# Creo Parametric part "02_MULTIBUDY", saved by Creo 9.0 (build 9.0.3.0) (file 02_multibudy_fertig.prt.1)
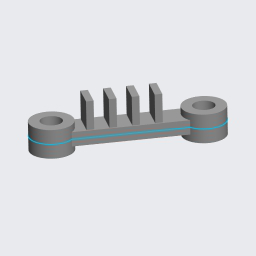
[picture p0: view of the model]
Materials in the file: S235JRG2

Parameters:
  BENENNUNG = "XXX"
  DATUM = "XX.XX.XX"
  ERSTELLER = "ARINDA"
  TEILETYP = "Fertigungsteil"
  PTC_MASTER_MATERIAL = "S235JRG2"
  SELECT_EN_NAME = "S235JRG2"
  SELECT_DIN_NAME = "RSt37-2"
  SELECT_DIN_NUMBER = "1.0038"
  SELECT_ASTM_NAME = "A 283 M Grade 2"
  MATERIAL_GROUP = "ME_ST_Baustahl"
  STANDARD_EN_DELIVERYSPEC = "DIN EN 10025"
  STANDARD_DIN_DELIVERYSPEC = "DIN 17100"

Other parameters: MASSE

Created from: ARINDA-STARTTEIL.PRT

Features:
  1. coordinate system "CS0"
  2. datum plane "DTM1", "T_RECHTS_Y-Z"
  3. datum plane "DTM2", "T_OBEN_X-Z"
  4. datum plane "DTM3", "T_VORNE_X-Y"
  5. datum axis "T_X-ACHSE"
  6. datum axis "A_1"
  7. datum axis "A_2"
  8. datum plane "DTM1", "P_SPIEGEL_1"
  9. datum plane "DTM2", "P_SPIEGEL_2"
  10. sketch "Skizze 1"
  11. extrusion "Profil 1"
  12. extrusion "Profil 2"
  13. pattern "Muster 1"
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
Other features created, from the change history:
  extrusion "Profil 3"
  extrusion "Profil 3 [3]"
  extrusion "Profil 3 [4]"
  extrusion "Profil 3 [2]"
  feature "Körper Trennen 1"

Other named items: T_BASIC, T_Y-ACHSE, T_Z-ACHSE

Layers: 00_STD-ACHSEN, 00_STD-EBENEN, 00_STD-KOORDSYS, 01_EBENEN, 01_KURVEN, KURVENELEMENTE, VOLUMENGEOMETRIE

Surfaces: 26 plane, 8 cylinder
